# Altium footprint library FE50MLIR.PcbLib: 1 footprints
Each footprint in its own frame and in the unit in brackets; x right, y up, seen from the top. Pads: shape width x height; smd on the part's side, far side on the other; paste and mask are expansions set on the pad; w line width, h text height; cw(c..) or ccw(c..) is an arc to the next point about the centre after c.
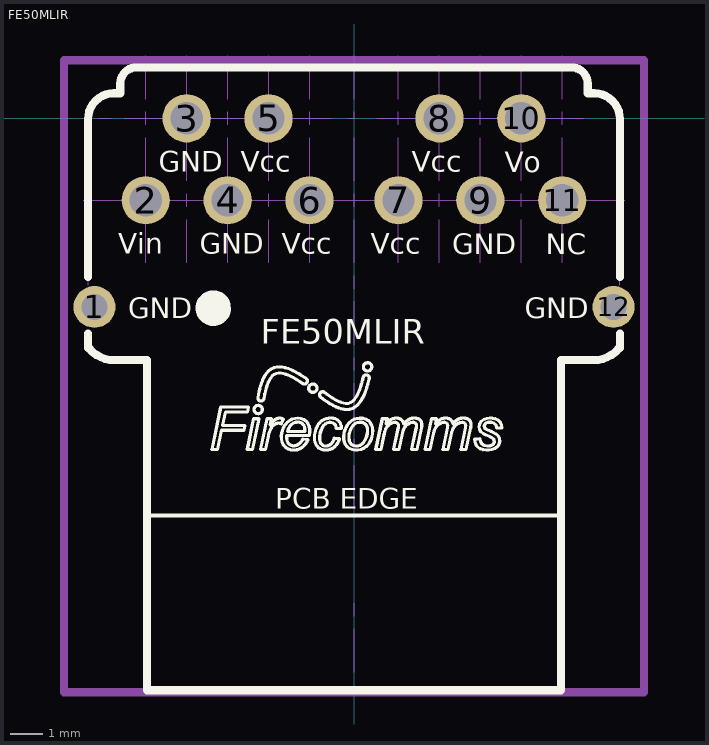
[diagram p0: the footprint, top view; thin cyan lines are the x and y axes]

## FE50MLIR [mm] "DC-50 Mb LC  Non-Inverting Tx, Inverting Rx"
height 11.8
pads (12):
  round 1.3 hole 0.8: 1(-8.05,-5.85) 12(8.05,-5.85)
  round 1.5 hole 1: 2(-6.46,-2.54) 3(-5.19,0) 4(-3.92,-2.54) 5(-2.65,0) 6(-1.38,-2.54) 7(1.38,-2.54) 8(2.65,0) 9(3.92,-2.54) 10(5.19,0) 11(6.46,-2.54)
Top Overlay:
  drawing of 797 lines, arcs and shapes, not listed
  text "PCB EDGE" at -2.438,-12.116 h0.64
  text "GND" at -6.05,-1.66 h0.64
  text "Vcc" at -3.51,-1.66 h0.64
  text "Vcc" at 1.79,-1.66 h0.64
  text "Vo" at 4.674,-1.676 h0.64
  text "GND" at -7,-6.2 h0.64
  text "GND" at 5.3,-6.2 h0.64
  text "Vin" at -7.32,-4.2 h0.64
  text "GND" at -4.78,-4.2 h0.64
  text "Vcc" at -2.24,-4.2 h0.64
  text "Vcc" at 0.52,-4.2 h0.64
  text "GND" at 3.048,-4.216 h0.64
  text "NC" at 5.944,-4.216 h0.64
  text "FE50MLIR" at -2.896,-6.985 h0.76
Mechanical 2:
  lines w0.254: -9,-17.8 -9,1.8 5.465,1.8 9,1.8 9,1.465 9,-17.8 -9,-17.8
Mechanical 19:
  drawing of 190 lines, arcs and shapes, not listed
  text "Edge of PCB}" at -5.651,-13.599 h1
3D body "LC Connector Assembly.stp": height 11.8, standoff -3.35, extent -8.25,-17.616 8.25,1.659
